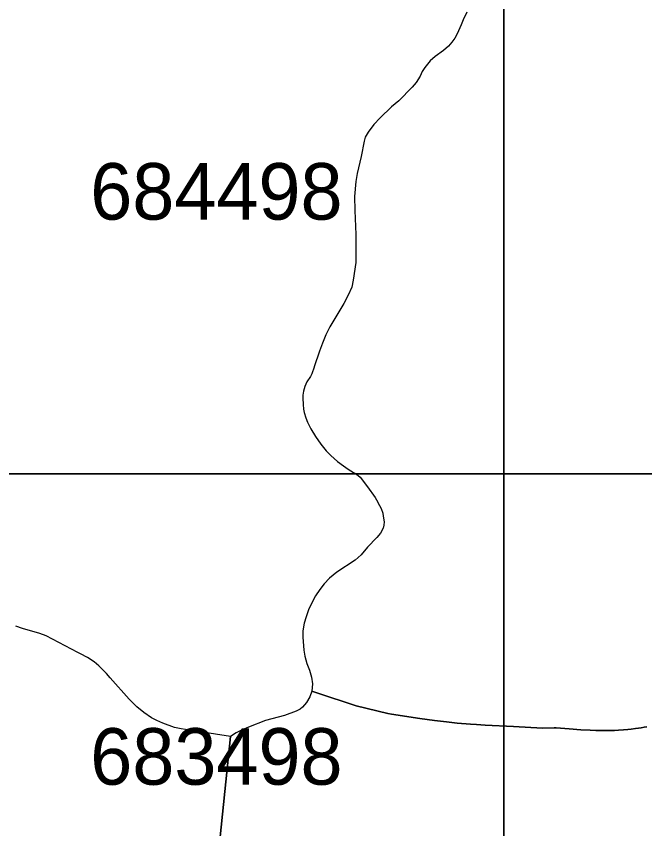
# Model space of a CAD drawing. Extents: x 25485000 to 25520000, y 6656775 to 6690000.
# Drawn here: x 25498138 to 25499249, y 6683372 to 6684810 of the extents above; entities that cross this region are included whole.
import ezdxf

# ---------------------------------------------------------------- set-up
doc = ezdxf.new("R2010")
doc.units = 0
doc.layers.add('Level 63', color=7, linetype='Continuous')

msp = doc.modelspace()

# ---------------------------------------------------------------- linework, layer by layer
at = {"layer": 'Level 63'}
for points in [[(25498000, 6684000), (25499000, 6684000), (25499000, 6685000), (25498000, 6685000)], [(25499000, 6684000), (25500000, 6684000), (25500000, 6685000), (25499000, 6685000)], [(25498000, 6683000), (25499000, 6683000), (25499000, 6684000), (25498000, 6684000)], [(25499000, 6683000), (25500000, 6683000), (25500000, 6684000), (25499000, 6684000)]]:
    msp.add_lwpolyline(points, close=True, dxfattribs=at)
for points in [[(25498934.3, 6684817.3), (25498927.8, 6684803.7), (25498924.5, 6684794.5), (25498917.6, 6684778.5), (25498913.1, 6684770.9), (25498908, 6684763.9), (25498902.1, 6684757.2), (25498893, 6684749.3), (25498878.3, 6684738.9), (25498869.5, 6684730.9), (25498860.2, 6684719.3), (25498855.7, 6684712), (25498851.8, 6684703.6), (25498845, 6684692.6), (25498838, 6684684.6), (25498814.1, 6684660.3), (25498801.5, 6684649.6), (25498781, 6684630.2), (25498770, 6684618.2), (25498760, 6684605), (25498754.8, 6684595.8), (25498752.8, 6684589), (25498747.6, 6684561.8), (25498740.7, 6684531.4), (25498738.1, 6684517.2), (25498736, 6684491.1), (25498736.3, 6684466), (25498738.1, 6684423.8), (25498738.5, 6684374.4), (25498733.8, 6684343.1), (25498731.1, 6684330.7), (25498724.5, 6684316.2), (25498716.8, 6684301.7), (25498692.4, 6684260), (25498685.3, 6684246), (25498679.3, 6684231.6), (25498673.8, 6684217), (25498664.4, 6684189.6), (25498664.4, 6684188.7), (25498660.4, 6684177.2), (25498657.8, 6684172.3), (25498651.7, 6684162.7), (25498647.8, 6684154.7), (25498645.6, 6684146.4), (25498644.7, 6684139.4), (25498644.6, 6684134.2), (25498644.8, 6684122.7), (25498645.5, 6684114.8), (25498646.8, 6684108.6), (25498649.5, 6684099.4), (25498652.7, 6684091.7), (25498658.5, 6684079.8), (25498667.1, 6684066.1), (25498676.5, 6684052.8), (25498685.9, 6684040.7), (25498694.1, 6684032.4), (25498706, 6684022), (25498716.3, 6684014.1), (25498724.6, 6684008.4), (25498734.2, 6684002.7), (25498739.3, 6683999.7), (25498745.8, 6683994.2), (25498759, 6683977.2), (25498772.3, 6683958.5), (25498774.8, 6683953.9), (25498780.1, 6683944), (25498782.8, 6683938.5), (25498785.7, 6683930.7), (25498786.8, 6683925.4), (25498788.2, 6683915.1), (25498787.9, 6683909.5), (25498786.7, 6683904.1), (25498782, 6683895), (25498775.1, 6683887.5), (25498758.8, 6683870.5), (25498747.9, 6683856.7), (25498736.8, 6683847.6), (25498704.5, 6683826.2), (25498691.8, 6683815.5), (25498682.3, 6683805.7), (25498674.4, 6683795.5), (25498666.9, 6683784.1), (25498660.4, 6683772.1), (25498654.8, 6683759.2), (25498650.3, 6683747.2), (25498646.9, 6683735.7), (25498644.6, 6683722.4), (25498644.5, 6683711.1), (25498646, 6683688.2), (25498648, 6683677.2), (25498651.4, 6683664.7), (25498656, 6683652.6), (25498659.6, 6683640.2), (25498661.3, 6683628.5), (25498660.6, 6683615.4)], [(25498498.1, 6683357.9), (25498516.5, 6683535.4), (25498436.7, 6683547.6), (25498429.2, 6683549.1), (25498417.7, 6683551.4), (25498396.7, 6683559), (25498386.2, 6683563.5), (25498376.9, 6683568.5), (25498363.4, 6683578), (25498350.7, 6683588.1), (25498337.5, 6683601.5), (25498304, 6683639.4), (25498297.5, 6683646.7), (25498283.8, 6683660.6), (25498275.4, 6683667.5), (25498263.8, 6683674.9), (25498251, 6683681.6), (25498246.4, 6683684.1), (25498190.4, 6683713.5), (25498179.3, 6683717.7), (25498148.4, 6683726.5), (25498136.8, 6683730.8)], [(25499253, 6683552.3), (25499248.3, 6683551.6), (25499242.9, 6683550.8), (25499238.2, 6683550.1), (25499232.7, 6683549.3), (25499224.9, 6683548.4), (25499219.1, 6683547.8), (25499211.4, 6683547.1), (25499202.9, 6683546.6), (25499195.5, 6683546.2), (25499187.8, 6683546), (25499177.3, 6683545.9), (25499170.3, 6683546), (25499162.6, 6683546.2), (25499152.8, 6683546.5), (25499136.4, 6683547.2), (25499115.4, 6683548.7), (25499092.7, 6683550.8), (25499089, 6683550.7), (25499068.2, 6683550.2), (25499017.1, 6683552.9), (25498967.1, 6683555.5), (25498951.8, 6683556.4), (25498941.1, 6683557.2), (25498917.4, 6683559.1), (25498898.5, 6683561), (25498877.1, 6683563.5), (25498851.5, 6683566.9), (25498801.4, 6683575.1), (25498794.7, 6683576.2), (25498738.9, 6683589.7), (25498669.2, 6683612.6), (25498660.6, 6683615.4), (25498656.7, 6683605.5), (25498650.8, 6683595.2), (25498644.1, 6683587), (25498639.6, 6683583.5), (25498632.7, 6683579.9), (25498611.9, 6683572.5), (25498578.5, 6683563.4), (25498548.1, 6683552), (25498536.9, 6683547.2), (25498526.6, 6683541.8), (25498516.5, 6683535.4)], [(25498660.6, 6683615.4), (25498669.2, 6683612.6), (25498738.9, 6683589.7), (25498794.7, 6683576.2), (25498801.4, 6683575.1), (25498851.5, 6683566.9), (25498877.1, 6683563.5), (25498898.5, 6683561), (25498917.4, 6683559.1), (25498941.1, 6683557.2), (25498951.8, 6683556.4), (25498967.1, 6683555.5), (25499017.1, 6683552.9), (25499068.2, 6683550.2), (25499089, 6683550.7), (25499092.7, 6683550.8), (25499115.4, 6683548.7), (25499136.4, 6683547.2), (25499152.8, 6683546.5), (25499162.6, 6683546.2), (25499170.3, 6683546), (25499177.3, 6683545.9), (25499187.8, 6683546), (25499195.5, 6683546.2), (25499202.9, 6683546.6), (25499211.4, 6683547.1), (25499219.1, 6683547.8), (25499224.9, 6683548.4), (25499232.7, 6683549.3), (25499238.2, 6683550.1), (25499242.9, 6683550.8), (25499248.3, 6683551.6), (25499253, 6683552.3)], [(25498516.5, 6683535.4), (25498498.1, 6683357.9)]]:
    msp.add_lwpolyline(points, dxfattribs=at)

# ---------------------------------------------------------------- texts
for s, p in [('684498', (25498268.5, 6684450)), ('683498', (25498268.5, 6683450))]:
    msp.add_text(s, height=100, dxfattribs=at).set_placement(p)

doc.saveas('drawing.dxf')
